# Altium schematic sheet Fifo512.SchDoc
size A4; DocumentNumber: 4; SheetNumber: 4; SheetTotal: 5
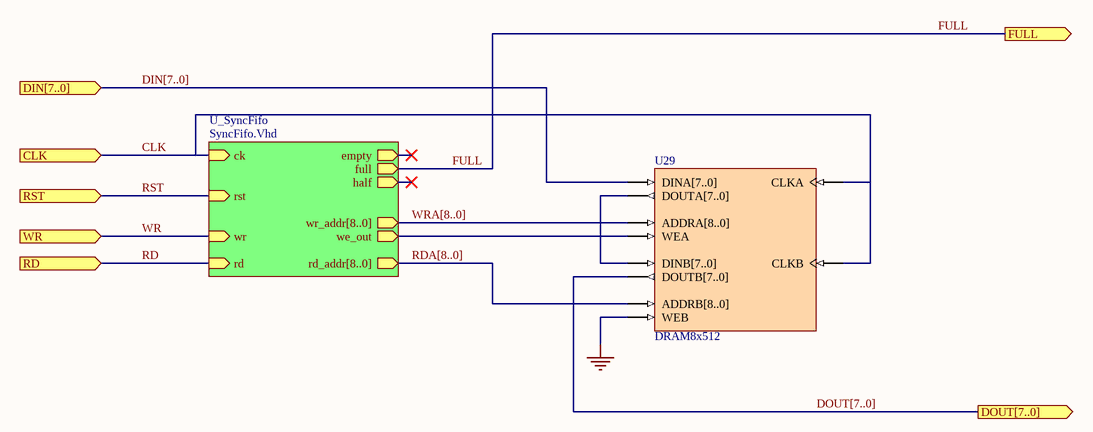
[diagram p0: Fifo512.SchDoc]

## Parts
U29  DRAM8x512

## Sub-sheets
U_SyncFifo = SyncFifo.Vhd: ck (in), empty (out), full (out), half (out), rd (in), rd_addr[8..0] (out), rst (in), we_out (out), wr (in), wr_addr[8..0] (out)  | VHDLENTITY: SyncFifo

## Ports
CLK (in), DIN[7..0] (in), DOUT[7..0] (out), FULL (out), RD (in), RST (in), WR (in)

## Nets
GND: U29.WEB
CLK: U29.CLKA U29.CLKB ; port CLK, sheet U_SyncFifo/ck
FULL: port FULL, sheet U_SyncFifo/full
RD: port RD, sheet U_SyncFifo/rd
RST: port RST, sheet U_SyncFifo/rst
WR: port WR, sheet U_SyncFifo/wr
NetU29_WEA: U29.WEA ; sheet U_SyncFifo/we_out

Not connected (* = marked no-connect by the designer): U29 ADDRA[8..0] ADDRB[8..0] DINA[7..0] DINB[7..0] DOUTA[7..0] DOUTB[7..0]

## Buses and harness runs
bus DIN[7..0] = port DIN[7..0]
bus DOUT[7..0] = port DOUT[7..0]
bus RDA[8..0] = sheet U_SyncFifo/rd_addr[8..0]
bus WRA[8..0] = sheet U_SyncFifo/wr_addr[8..0]

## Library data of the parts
U29 = DRAM8x512: Dual Port Random Access Memory 512 x 8 and 512 x 8; Memory_DepthA: 512; Memory_Type: RAM_DualPortBlock; Memory_WidthA: 8; Memory_ClockEdge: Rising; Nexus_Core: Memory_Program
